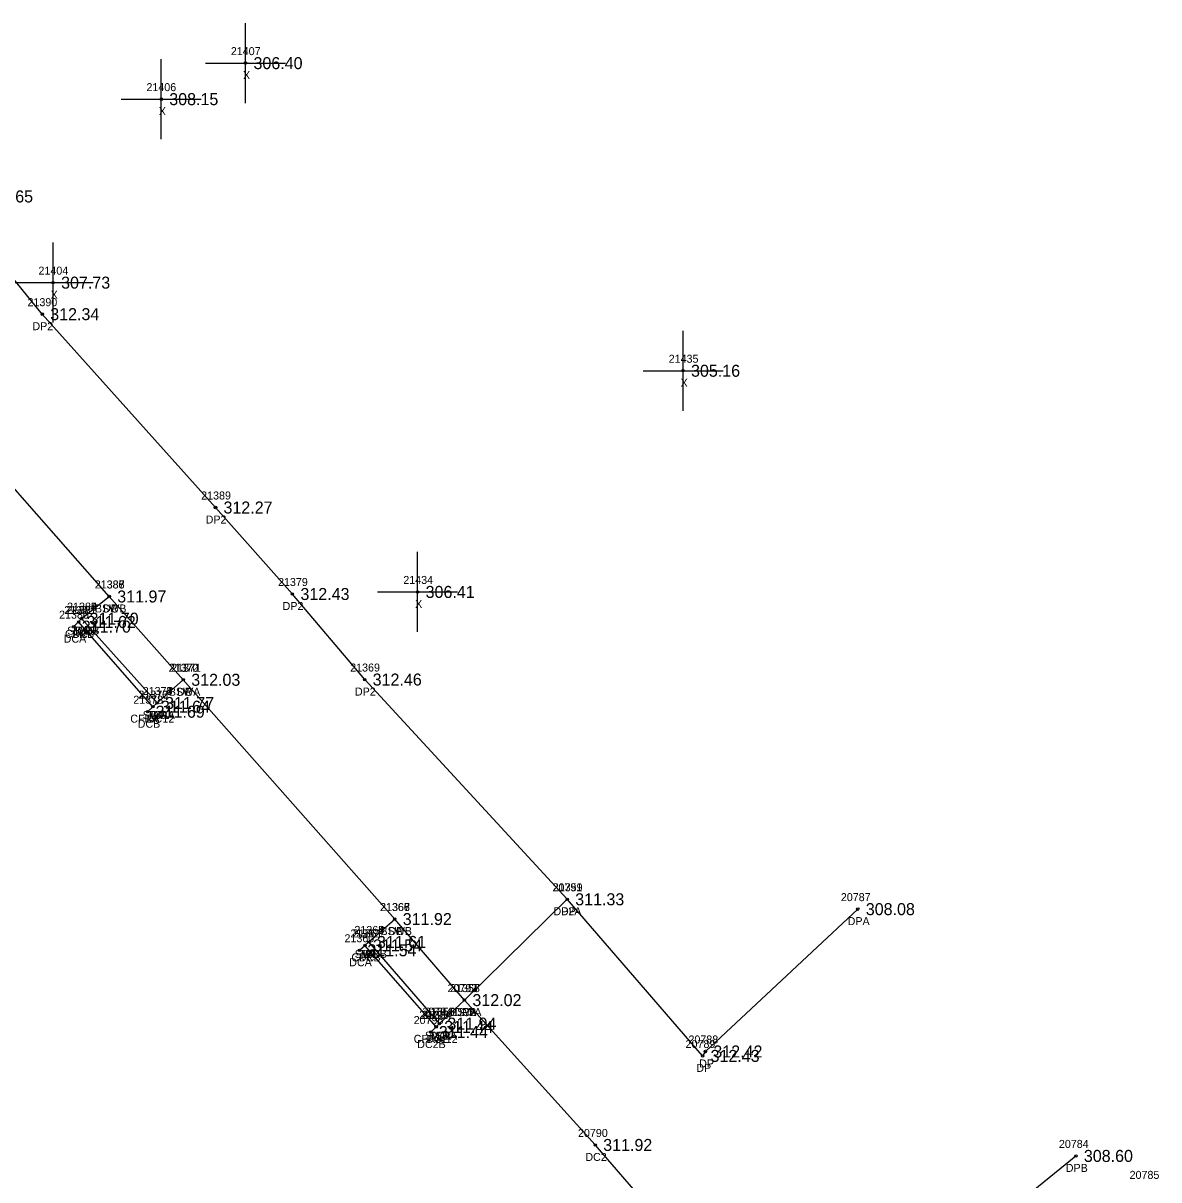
# Model space of a CAD drawing. Extents: x 1970242 to 1971082, y 803104 to 803947.
# Drawn here: x 1970429 to 1970571, y 803734.7 to 803879.3 of the extents above; entities that cross this region are included whole.
import ezdxf

# ---------------------------------------------------------------- set-up
doc = ezdxf.new("R2010")
doc.units = 0
for name, color, linetype in [('RD_DTM_BkLn2', 7, 'Continuous'), ('RD_EX_Conc', 7, 'Continuous'), ('RD_EX_Conc_txCode', 7, 'Continuous'), ('RD_EX_Driveway', 7, 'Continuous'), ('RD_EX_Driveway_txCode', 7, 'Continuous'), ('RD_EX_Misc', 7, 'Continuous'), ('RD_EX_Misc_txCode', 7, 'Continuous'), ('RD_EX_TX_Conc_ELEV', 7, 'Continuous'), ('RD_EX_TX_Driveway_ELEV', 7, 'Continuous'), ('RD_EX_TX_Misc_ELEV', 7, 'Continuous'), ('RD_SMD_Locator', 7, 'Continuous')]:
    doc.layers.add(name, color=color, linetype=linetype)

msp = doc.modelspace()

# ---------------------------------------------------------------- linework, layer by layer
at = {"layer": 'RD_DTM_BkLn2'}
for p, q in [((1970445.78, 803794.3), (1970436.33, 803804.84)), ((1970481.07, 803754.23), (1970472.27, 803764.44))]:
    msp.add_line(p, q, dxfattribs=at)
at = {"layer": 'RD_EX_Conc'}
for p, q in [((1970449.05, 803797.2), (1970439.8, 803807.61)), ((1970445.78, 803794.3), (1970436.33, 803804.84)), ((1970445.25, 803793.84), (1970435.97, 803804.43)), ((1970484.2, 803757.17), (1970475.49, 803767.3)), ((1970481.07, 803754.23), (1970472.27, 803764.44)), ((1970480.67, 803753.83), (1970471.77, 803764.01))]:
    msp.add_line(p, q, dxfattribs=at)
for points in [[(1970435.37, 803803.84), (1970435.97, 803804.43), (1970436.33, 803804.84), (1970439.8, 803807.61), (1970418.95, 803831.27), (1970412.58, 803837.88), (1970409.39, 803835.52), (1970408.92, 803835.11), (1970408.19, 803834.27)], [(1970471.07, 803763.4), (1970471.77, 803764.01), (1970472.27, 803764.44), (1970475.49, 803767.3), (1970449.05, 803797.2), (1970445.78, 803794.3), (1970445.25, 803793.84), (1970444.6, 803793.21)], [(1970522.11, 803705.63), (1970526.01, 803709.22), (1970523.91, 803712.04), (1970500.55, 803739.07), (1970484.2, 803757.17), (1970481.07, 803754.23), (1970480.67, 803753.83), (1970480, 803753.18)]]:
    msp.add_lwpolyline(points, dxfattribs=at)
at = {"layer": 'RD_EX_Driveway'}
for points in [[(1970497.05, 803769.77), (1970471.73, 803797.23), (1970462.7, 803807.92), (1970453.08, 803818.73), (1970431.42, 803842.89), (1970421.38, 803855.24), (1970409.25, 803850.65), (1970404.02, 803848.54)], [(1970484.2, 803757.17), (1970475.49, 803767.3), (1970449.05, 803797.2), (1970439.8, 803807.61), (1970418.95, 803831.27), (1970412.58, 803837.88)], [(1970533.38, 803768.54), (1970514.32, 803750.75), (1970513.97, 803750.2), (1970497.05, 803769.77), (1970484.2, 803757.17)], [(1970523.91, 803712.04), (1970531.77, 803719.59), (1970534.87, 803716.79), (1970560.64, 803737.7)]]:
    msp.add_lwpolyline(points, dxfattribs=at)
at = {"layer": 'RD_EX_Misc'}
for p, q in [((1970456.83, 803869.26), (1970456.83, 803879.26)), ((1970446.3, 803864.76), (1970446.3, 803874.76)), ((1970451.83, 803874.26), (1970461.83, 803874.26)), ((1970441.3, 803869.76), (1970451.3, 803869.76)), ((1970432.78, 803841.83), (1970432.78, 803851.83)), ((1970427.78, 803846.83), (1970437.78, 803846.83)), ((1970511.53, 803830.82), (1970511.53, 803840.82)), ((1970506.53, 803835.82), (1970516.53, 803835.82)), ((1970478.35, 803803.18), (1970478.35, 803813.18)), ((1970473.35, 803808.18), (1970483.35, 803808.18))]:
    msp.add_line(p, q, dxfattribs=at)
at = {"layer": 'RD_SMD_Locator'}
for centre in [(1970456.83, 803874.26), (1970446.3, 803869.76), (1970432.78, 803846.83), (1970431.42, 803842.89), (1970511.53, 803835.82), (1970453.08, 803818.73), (1970439.8, 803807.61), (1970439.8, 803807.61), (1970439.8, 803807.61), (1970462.7, 803807.92), (1970478.35, 803808.18), (1970436.33, 803804.84), (1970436.33, 803804.84), (1970436.33, 803804.84), (1970435.37, 803803.84), (1970435.97, 803804.43), (1970435.97, 803804.43), (1970449.05, 803797.2), (1970449.05, 803797.2), (1970449.05, 803797.2), (1970471.73, 803797.23), (1970444.6, 803793.21), (1970445.25, 803793.84), (1970445.25, 803793.84), (1970445.78, 803794.3), (1970445.78, 803794.3), (1970445.78, 803794.3), (1970497.05, 803769.77), (1970497.05, 803769.77), (1970533.38, 803768.54), (1970475.49, 803767.3), (1970475.49, 803767.3), (1970475.49, 803767.3), (1970471.77, 803764.01), (1970471.77, 803764.01), (1970472.27, 803764.44), (1970472.27, 803764.44), (1970472.27, 803764.44), (1970471.07, 803763.4), (1970484.2, 803757.17), (1970484.2, 803757.17), (1970484.2, 803757.17), (1970484.2, 803757.17), (1970481.07, 803754.23), (1970481.07, 803754.23), (1970481.07, 803754.23), (1970480, 803753.18), (1970480.67, 803753.83), (1970480.67, 803753.83), (1970513.97, 803750.2), (1970514.32, 803750.75), (1970500.55, 803739.07), (1970560.64, 803737.7)]:
    msp.add_circle(centre, 0.15, dxfattribs=at)

# ---------------------------------------------------------------- texts
at = {"layer": 'RD_EX_Conc_txCode'}
for s, p in [('21386', (1970437.98, 803808.61)), ('21388', (1970438, 803808.61)), ('21382', (1970434.18, 803805.43)), ('21381', (1970434.46, 803805.43)), ('21383', (1970434.53, 803805.84)), ('21384', (1970434.53, 803805.84)), ('21385', (1970434.53, 803805.84)), ('BSWB', (1970438.01, 803805.61)), ('DC', (1970439.02, 803805.61)), ('21380', (1970433.53, 803804.84)), ('CFRB', (1970434.27, 803802.43)), ('SWRB', (1970434.54, 803802.84)), ('TCB', (1970435.06, 803802.84)), ('DC', (1970435.19, 803802.43)), ('DC', (1970435.55, 803802.84)), ('DCA', (1970434.1, 803801.84)), ('21372', (1970447.26, 803798.2)), ('21371', (1970447.54, 803798.2)), ('21373', (1970443.98, 803795.3)), ('21374', (1970443.98, 803795.3)), ('21375', (1970443.98, 803795.3)), ('BSWA', (1970447.25, 803795.2)), ('DC', (1970448.27, 803795.2)), ('21378', (1970442.81, 803794.21)), ('21376', (1970443.43, 803794.84)), ('21377', (1970443.46, 803794.84)), ('SWRA', (1970443.98, 803792.3)), ('TCA', (1970444.5, 803792.3)), ('DC', (1970445, 803792.3)), ('CFRA 12', (1970442.43, 803791.84)), ('DCB', (1970443.35, 803791.21)), ('DC', (1970444.47, 803791.84)), ('21366', (1970473.64, 803768.3)), ('21368', (1970473.67, 803768.3)), ('21362', (1970469.95, 803765.01)), ('21361', (1970470.23, 803765.01)), ('21363', (1970470.45, 803765.44)), ('21364', (1970470.45, 803765.44)), ('21365', (1970470.45, 803765.44)), ('BSWB', (1970473.7, 803765.3)), ('DC', (1970474.71, 803765.3)), ('21360', (1970469.21, 803764.4)), ('CFRB', (1970470.07, 803762.01)), ('SWRB', (1970470.49, 803762.44)), ('TCB', (1970471.01, 803762.44)), ('DC', (1970470.99, 803762.01)), ('DC', (1970471.49, 803762.44)), ('DCA', (1970469.8, 803761.4)), ('20793', (1970482.09, 803758.17)), ('21357', (1970482.41, 803758.17)), ('20795', (1970478.55, 803754.83)), ('21354', (1970478.87, 803754.83)), ('20794', (1970478.95, 803755.23)), ('21356', (1970479.25, 803755.23)), ('21355', (1970479.28, 803755.23)), ('BSWA', (1970482.4, 803755.17)), ('DC2', (1970482.98, 803755.17)), ('20796', (1970477.86, 803754.18)), ('CFRA 12', (1970477.85, 803751.83)), ('SWRA', (1970479.27, 803752.23)), ('DC2', (1970479.44, 803751.83)), ('TCA', (1970479.79, 803752.23)), ('DC2', (1970479.84, 803752.23)), ('DC2B', (1970478.3, 803751.18)), ('20790', (1970498.4, 803740.07)), ('DC2', (1970499.32, 803737.07)), ('20785', (1970567.36, 803734.83))]:
    msp.add_text(s, height=1, dxfattribs=at).set_placement(p)
at = {"layer": 'RD_EX_Driveway_txCode'}
for s, p in [('21390', (1970429.58, 803843.89)), ('DP2', (1970430.19, 803840.89)), ('21389', (1970451.29, 803819.73)), ('DP2', (1970451.85, 803816.73)), ('21387', (1970438, 803808.61)), ('21379', (1970460.9, 803808.92)), ('DP', (1970439.02, 803805.61)), ('DP2', (1970461.47, 803805.92)), ('21370', (1970447.22, 803798.2)), ('21369', (1970469.92, 803798.23)), ('DP', (1970448.27, 803795.2)), ('DP2', (1970470.51, 803795.23)), ('20791', (1970495.21, 803770.77)), ('21359', (1970495.25, 803770.77)), ('20787', (1970531.26, 803769.54)), ('21367', (1970473.67, 803768.3)), ('DP2A', (1970495.33, 803767.77)), ('DP', (1970496.27, 803767.77)), ('DPA', (1970532.11, 803766.54)), ('DP', (1970474.71, 803765.3)), ('20792', (1970482.09, 803758.17)), ('21358', (1970482.41, 803758.17)), ('DPA', (1970482.94, 803755.17)), ('DPB', (1970482.95, 803755.17)), ('20788', (1970512.21, 803751.75)), ('20789', (1970511.85, 803751.2)), ('DP', (1970513.54, 803748.75)), ('DP', (1970513.19, 803748.2)), ('20784', (1970558.52, 803738.7)), ('DPB', (1970559.38, 803735.7))]:
    msp.add_text(s, height=1, dxfattribs=at).set_placement(p)
at = {"layer": 'RD_EX_Misc_txCode'}
for s, p in [('21407', (1970455, 803875.26)), ('X', (1970456.52, 803872.26)), ('21406', (1970444.45, 803870.76)), ('X', (1970445.99, 803867.76)), ('21404', (1970430.95, 803847.83)), ('X', (1970432.47, 803844.83)), ('21435', (1970509.74, 803836.82)), ('X', (1970511.22, 803833.82)), ('21434', (1970476.56, 803809.18)), ('X', (1970478.04, 803806.18))]:
    msp.add_text(s, height=1, dxfattribs=at).set_placement(p)
at = {"layer": 'RD_EX_TX_Conc_ELEV'}
for s, p in [('311.97', (1970440.8, 803806.86)), ('311.97', (1970440.8, 803806.86)), ('311.62', (1970436.97, 803803.68)), ('311.62', (1970436.97, 803803.68)), ('311.70', (1970437.33, 803804.09)), ('311.70', (1970437.33, 803804.09)), ('311.70', (1970437.33, 803804.09)), ('311.70', (1970436.37, 803803.09)), ('312.03', (1970450.05, 803796.45)), ('312.03', (1970450.05, 803796.45)), ('311.64', (1970446.25, 803793.09)), ('311.64', (1970446.25, 803793.09)), ('311.77', (1970446.78, 803793.55)), ('311.77', (1970446.78, 803793.55)), ('311.77', (1970446.78, 803793.55)), ('311.69', (1970445.6, 803792.46)), ('311.92', (1970476.49, 803766.55)), ('311.92', (1970476.49, 803766.55)), ('311.54', (1970472.07, 803762.65)), ('311.54', (1970472.77, 803763.26)), ('311.54', (1970472.77, 803763.26)), ('311.61', (1970473.27, 803763.69)), ('311.61', (1970473.27, 803763.69)), ('311.61', (1970473.27, 803763.69)), ('312.02', (1970485.2, 803756.42)), ('312.02', (1970485.2, 803756.42)), ('311.44', (1970481.67, 803753.08)), ('311.44', (1970481.67, 803753.08)), ('311.94', (1970482.07, 803753.48)), ('311.94', (1970482.07, 803753.48)), ('311.94', (1970482.07, 803753.48)), ('311.44', (1970481, 803752.43)), ('311.92', (1970501.55, 803738.32))]:
    msp.add_text(s, height=1.5, dxfattribs=at).set_placement(p)
at = {"layer": 'RD_EX_TX_Driveway_ELEV'}
for s, p in [('312.34', (1970432.42, 803842.14)), ('312.27', (1970454.08, 803817.98)), ('311.97', (1970440.8, 803806.86)), ('312.43', (1970463.7, 803807.17)), ('312.03', (1970450.05, 803796.45)), ('312.46', (1970472.73, 803796.48)), ('311.33', (1970498.05, 803769.02)), ('311.33', (1970498.05, 803769.02)), ('308.08', (1970534.38, 803767.79)), ('311.92', (1970476.49, 803766.55)), ('312.02', (1970485.2, 803756.42)), ('312.02', (1970485.2, 803756.42)), ('312.42', (1970515.32, 803750)), ('312.43', (1970514.97, 803749.45)), ('308.60', (1970561.64, 803736.95))]:
    msp.add_text(s, height=1.5, dxfattribs=at).set_placement(p)
at = {"layer": 'RD_EX_TX_Misc_ELEV'}
for s, p in [('306.40', (1970457.83, 803873.51)), ('308.15', (1970447.3, 803869.01)), ('308.65', (1970424.14, 803856.85)), ('307.73', (1970433.78, 803846.08)), ('305.16', (1970512.53, 803835.07)), ('306.41', (1970479.35, 803807.43))]:
    msp.add_text(s, height=1.5, dxfattribs=at).set_placement(p)

doc.saveas('drawing.dxf')
